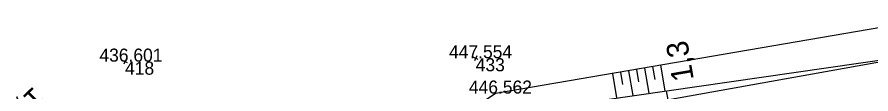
# Model space of a CAD drawing. Extents: x -751615 to -750797, y -1114905 to -1114561.
# Drawn here: x -751104 to -751025.5, y -1114641.5 to -1114634.8 of the extents above; entities that cross this region are included whole.
import ezdxf

# ---------------------------------------------------------------- set-up
doc = ezdxf.new("R2010")
doc.units = 0
for name, color, linetype in [('Vrstva 48', 7, 'Continuous'), ('Vrstva 49', 7, 'Continuous'), ('Vrstva 60', 7, 'Continuous'), ('Vrstva 61', 7, 'Continuous')]:
    doc.layers.add(name, color=color, linetype=linetype)

msp = doc.modelspace()

# ---------------------------------------------------------------- linework, layer by layer
at = {"layer": 'Vrstva 48'}
for p, q in [((-751046.335, -1114639.267), (-751045.936, -1114641.594)), ((-751045.596, -1114639.14), (-751045.395, -1114640.313)), ((-751044.857, -1114639.013), (-751044.451, -1114641.38)), ((-751049.292, -1114639.775), (-751048.906, -1114642.022)), ((-751048.553, -1114639.648), (-751048.358, -1114640.781)), ((-751047.814, -1114639.521), (-751047.421, -1114641.808)), ((-751047.074, -1114639.394), (-751046.876, -1114640.547)), ((-751044.158, -1114642.198), (-751044.308, -1114641.359))]:
    msp.add_line(p, q, dxfattribs=at)
at = {"layer": 'Vrstva 49'}
for p, q in [((-751058.95, -1114643.469), (-751019.246, -1114637.748)), ((-751093.886, -1114638.792), (-751094.336, -1114638.572)), ((-751094.001, -1114638.457), (-751094.221, -1114638.907)), ((-751061.634, -1114638.478), (-751062.084, -1114638.26)), ((-751061.75, -1114638.144), (-751061.968, -1114638.594))]:
    msp.add_line(p, q, dxfattribs=at)
for points in [[(-751020.117, -1114634.765), (-751060.04, -1114641.62), (-751070.127, -1114648.352), (-751076.528, -1114658.314), (-751078.11, -1114663.715)], [(-751019.246, -1114637.748), (-751058.49, -1114644.759), (-751068.921, -1114649.956), (-751075.459, -1114658.878), (-751078.11, -1114663.715)]]:
    msp.add_lwpolyline(points, dxfattribs=at)
at = {"layer": 'Vrstva 60'}
for p, q in [((-751061.859, -1114638.369), (-751061.859, -1114638.369)), ((-751094.111, -1114638.682), (-751094.111, -1114638.682))]:
    msp.add_line(p, q, dxfattribs=at)

# ---------------------------------------------------------------- texts
at = {"layer": 'Vrstva 48'}
for s, rotation, p in [('1,3', 99.74299, (-751041.789, -1114640.312)), ('1,1', 224.83025, (-751102.533, -1114640.88))]:
    msp.add_text(s, height=2, rotation=rotation, dxfattribs=at).set_placement(p)
at = {"layer": 'Vrstva 60'}
for s, p in [('433', (-751061.859, -1114639.569)), ('418', (-751094.111, -1114639.882))]:
    msp.add_text(s, height=1.2, dxfattribs=at).set_placement(p)
at = {"layer": 'Vrstva 61'}
for s, p in [('436.601', (-751096.468, -1114638.682)), ('447.554', (-751064.31, -1114638.369)), ('446.562', (-751062.488, -1114641.62))]:
    msp.add_text(s, height=1.2, dxfattribs=at).set_placement(p)

doc.saveas('drawing.dxf')
